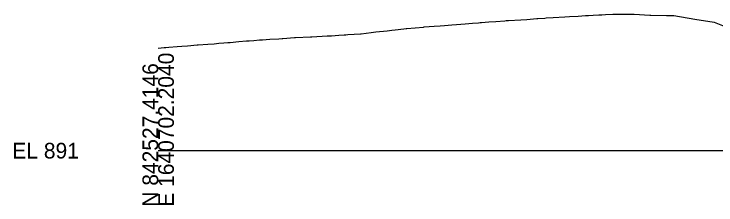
# Model space of a CAD drawing. Extents: x -26 to 1640245, y -10 to 842531.
# Drawn here: x -25.7 to 99.4, y 990.3 to 1024.4 of the extents above; entities that cross this region are included whole.
import ezdxf

# ---------------------------------------------------------------- set-up
doc = ezdxf.new("R2010")
doc.units = 0
for name, color, linetype in [('Default', 7, 'Continuous'), ('Exist Cross Section Cell', 7, 'Continuous'), ('Exist XS Ground Line', 7, 'Continuous')]:
    doc.layers.add(name, color=color, linetype=linetype)

msp = doc.modelspace()

# ---------------------------------------------------------------- linework, layer by layer
at = {"layer": 'Exist Cross Section Cell'}
msp.add_line((0, 1000), (150, 1000), dxfattribs=at)
at = {"layer": 'Exist XS Ground Line'}
for p, q in [((65.69, 1023.43), (67.47, 1023.57)), ((67.47, 1023.57), (67.52, 1023.57)), ((67.52, 1023.57), (67.55, 1023.57)), ((67.55, 1023.57), (67.67, 1023.58)), ((67.67, 1023.58), (68.91, 1023.66)), ((68.91, 1023.66), (69.13, 1023.68)), ((69.13, 1023.68), (70.43, 1023.76)), ((70.43, 1023.76), (72.51, 1023.88)), ((72.51, 1023.88), (73.31, 1023.93)), ((73.31, 1023.93), (74.85, 1024.02)), ((74.85, 1024.02), (76.19, 1024.09)), ((76.19, 1024.09), (76.69, 1024.12)), ((76.69, 1024.12), (77.55, 1024.16)), ((77.55, 1024.16), (78.52, 1024.22)), ((78.52, 1024.22), (79.07, 1024.26)), ((79.07, 1024.26), (79.72, 1024.28)), ((79.72, 1024.28), (81.05, 1024.35)), ((81.05, 1024.35), (81.88, 1024.37)), ((81.88, 1024.37), (81.95, 1024.37)), ((81.95, 1024.37), (82.6, 1024.37)), ((82.6, 1024.37), (84.83, 1024.38)), ((84.83, 1024.38), (87.64, 1024.2)), ((87.64, 1024.2), (87.71, 1024.19)), ((87.71, 1024.19), (87.79, 1024.19)), ((87.79, 1024.19), (90.58, 1024.12)), ((90.58, 1024.12), (91.45, 1024.1)), ((91.45, 1024.1), (91.91, 1024.09)), ((91.91, 1024.09), (95.64, 1023.49)), ((95.64, 1023.49), (99.12, 1022.93)), ((47.4, 1022.07), (49.2, 1022.21)), ((49.2, 1022.21), (50.28, 1022.29)), ((50.28, 1022.29), (51.03, 1022.36)), ((51.03, 1022.36), (52.34, 1022.46)), ((52.34, 1022.46), (53.16, 1022.53)), ((53.16, 1022.53), (54.7, 1022.64)), ((54.7, 1022.64), (56.04, 1022.76)), ((56.04, 1022.76), (57.11, 1022.84)), ((57.11, 1022.84), (57.4, 1022.86)), ((57.4, 1022.86), (57.63, 1022.88)), ((57.63, 1022.88), (58.92, 1022.96)), ((58.92, 1022.96), (60.19, 1023.05)), ((60.19, 1023.05), (61.8, 1023.18)), ((61.8, 1023.18), (62.03, 1023.2)), ((62.03, 1023.2), (62.43, 1023.23)), ((62.43, 1023.23), (64.67, 1023.37)), ((64.67, 1023.37), (65.69, 1023.43)), ((99.12, 1022.93), (100.9, 1022.23)), ((36.17, 1020.87), (37.99, 1021.09)), ((37.99, 1021.09), (38.77, 1021.18)), ((38.77, 1021.18), (40.82, 1021.4)), ((40.82, 1021.4), (41.64, 1021.48)), ((41.64, 1021.48), (42.26, 1021.56)), ((42.26, 1021.56), (43.76, 1021.72)), ((43.76, 1021.72), (44.23, 1021.77)), ((44.23, 1021.77), (44.28, 1021.78)), ((44.28, 1021.78), (44.32, 1021.78)), ((44.32, 1021.78), (47.3, 1022.06)), ((47.3, 1022.06), (47.4, 1022.07)), ((17.05, 1019.67), (18.05, 1019.75)), ((18.05, 1019.75), (18.61, 1019.79)), ((18.61, 1019.79), (19.88, 1019.87)), ((19.88, 1019.87), (21.49, 1019.98)), ((21.49, 1019.98), (22.09, 1020.03)), ((22.09, 1020.03), (22.22, 1020.03)), ((22.22, 1020.03), (24.29, 1020.17)), ((24.29, 1020.17), (24.5, 1020.18)), ((24.5, 1020.18), (27.13, 1020.32)), ((27.13, 1020.32), (27.21, 1020.33)), ((27.21, 1020.33), (27.25, 1020.33)), ((27.25, 1020.33), (27.4, 1020.34)), ((27.4, 1020.34), (30.13, 1020.48)), ((30.13, 1020.48), (30.87, 1020.52)), ((30.87, 1020.52), (32.18, 1020.59)), ((32.18, 1020.59), (33.16, 1020.65)), ((33.16, 1020.65), (33.45, 1020.67)), ((33.45, 1020.67), (33.83, 1020.7)), ((33.83, 1020.7), (36.09, 1020.86)), ((36.09, 1020.86), (36.16, 1020.87)), ((36.16, 1020.87), (36.17, 1020.87)), ((1.34, 1018.4), (1.92, 1018.45)), ((1.92, 1018.45), (3.39, 1018.57)), ((3.39, 1018.57), (4.22, 1018.65)), ((4.22, 1018.65), (5.22, 1018.73)), ((5.22, 1018.73), (6.97, 1018.86)), ((6.97, 1018.86), (7.05, 1018.87)), ((7.05, 1018.87), (7.1, 1018.87)), ((7.1, 1018.87), (8.88, 1019)), ((8.88, 1019), (9.98, 1019.09)), ((9.98, 1019.09), (10.79, 1019.16)), ((10.79, 1019.16), (11.68, 1019.24)), ((11.68, 1019.24), (12.42, 1019.29)), ((12.42, 1019.29), (12.86, 1019.33)), ((12.86, 1019.33), (14.38, 1019.45)), ((14.38, 1019.45), (15.74, 1019.57)), ((15.74, 1019.57), (16.21, 1019.61)), ((16.21, 1019.61), (17.05, 1019.67)), ((0, 1018.29), (1.09, 1018.38)), ((1.09, 1018.38), (1.34, 1018.4))]:
    msp.add_line(p, q, dxfattribs=at)

# ---------------------------------------------------------------- texts
at = {"layer": 'Default'}
msp.add_text('-', height=0.0001, dxfattribs=at).set_placement((0, 1000))
at = {"layer": 'Exist Cross Section Cell'}
for s, p in [('E 1640702.2040', (2.8, 990)), ('N 842527.4146', (0, 990))]:
    msp.add_text(s, height=2.8, rotation=90, dxfattribs=at).set_placement(p)
msp.add_text('EL 891', height=2.8, dxfattribs=at).set_placement((-26, 998.6))

doc.saveas('drawing.dxf')
